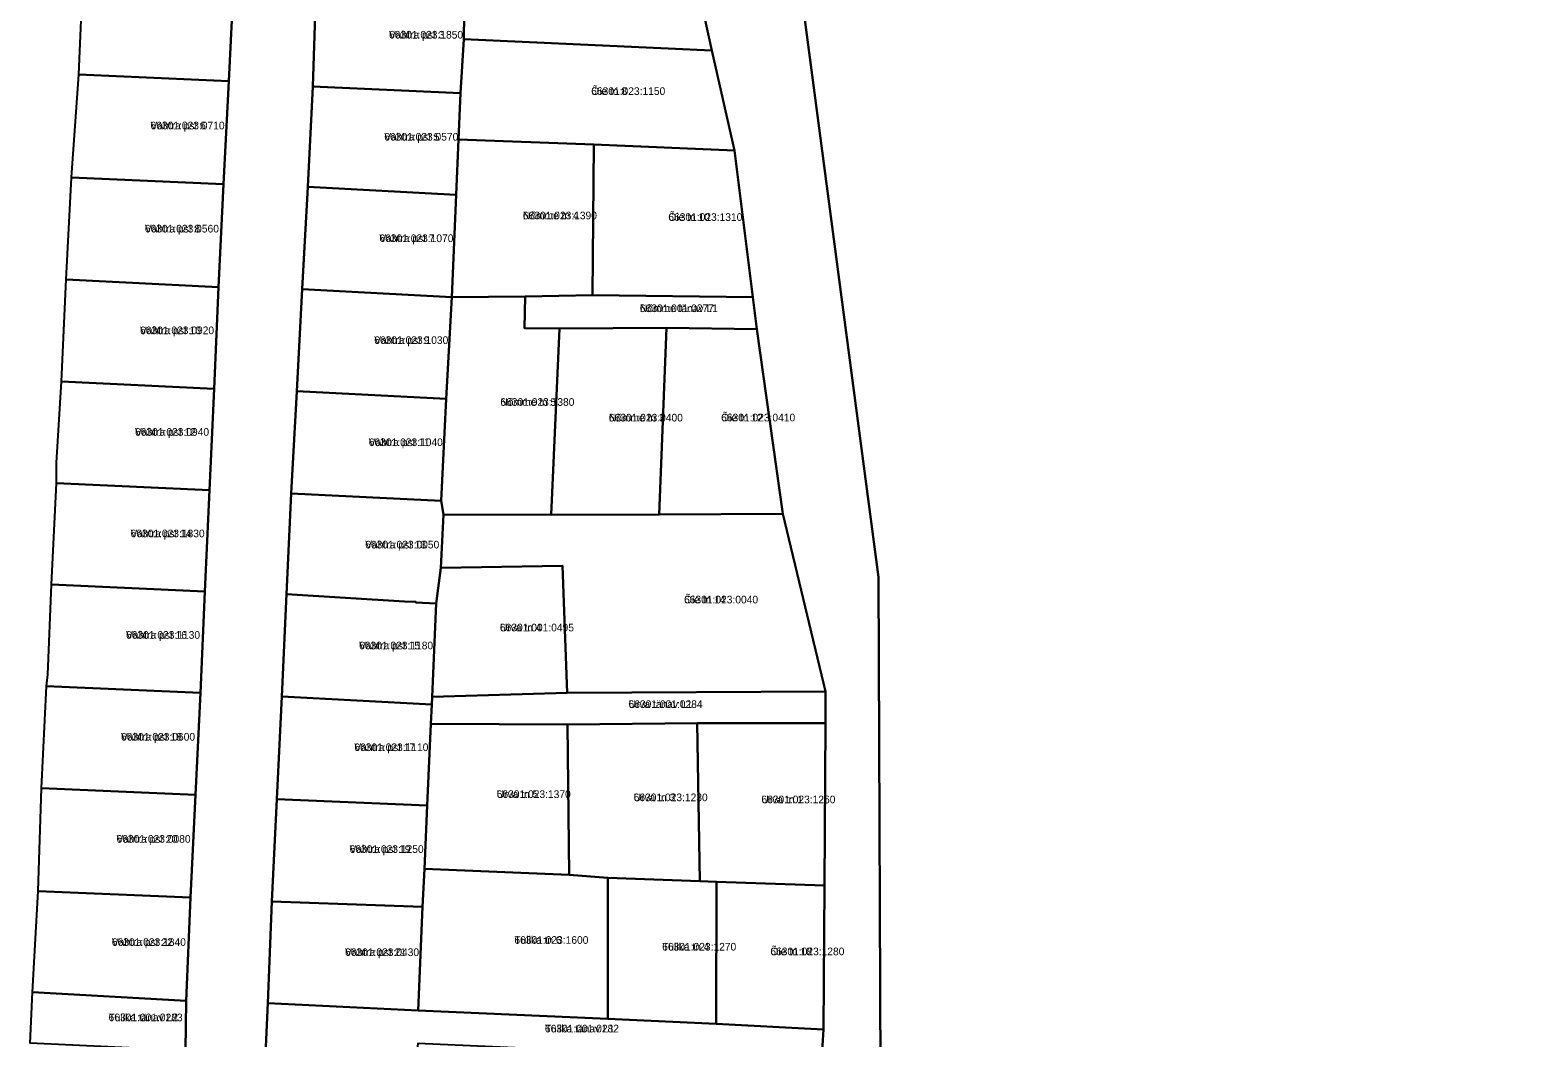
# Model space of a CAD drawing. Extents: x 632278 to 636344, y 6578401 to 6583362.
# Drawn here: x 633485.7 to 633781, y 6580259.1 to 6580456.5 of the extents above; entities that cross this region are included whole.
import ezdxf

# ---------------------------------------------------------------- set-up
doc = ezdxf.new("R2010")
doc.units = 0
for name, color, linetype in [('L_AADRESS', 7, 'Continuous'), ('PIIR', 7, 'Continuous'), ('TUNNUS', 7, 'Continuous')]:
    doc.layers.add(name, color=color, linetype=linetype)

msp = doc.modelspace()

# ---------------------------------------------------------------- linework, layer by layer
at = {"layer": 'PIIR'}
for points in [[(633605.51, 6579809.61), (633653.33, 6579978.24), (633651.84, 6580349.33), (633626.29, 6580542.71), (633673.01, 6580549.14), (633700.61, 6580504.19), (633703.74, 6580499.02), (633730.56, 6580496.56), (633754.85, 6580494.35), (633873.24, 6580487.78), (633957.63, 6580253.07), (633845.55, 6580021.57), (633842.59, 6580023.82), (633825.34, 6579983.05), (633800.65, 6579928), (633788.44, 6579901.57)], [(633626.29, 6580542.71), (633651.84, 6580349.33), (633653.33, 6579978.24), (633605.51, 6579809.61)], [(633640.7, 6580254.39), (633641.05, 6580260.68), (633641.28, 6580288.9), (633641.48, 6580320.75), (633641.44, 6580326.91), (633633.12, 6580361.74), (633628.04, 6580397.95), (633627.26, 6580404.2), (633623.67, 6580432.92), (633619.23, 6580452.53), (633613.69, 6580477.6)], [(633516.13, 6580256.6), (633516.28, 6580266.34), (633517.1, 6580286.58), (633518.11, 6580306.65), (633519.04, 6580326.64), (633519.93, 6580346.51), (633520.82, 6580366.38), (633521.71, 6580386.25), (633522.61, 6580406.13), (633523.54, 6580426.35), (633524.58, 6580446.52), (633525.58, 6580466.52)], [(633541.72, 6580465.57), (633541.03, 6580445.51), (633540.05, 6580425.81), (633538.98, 6580405.78), (633537.9, 6580385.76), (633536.82, 6580365.73), (633535.93, 6580346), (633534.97, 6580325.92), (633534, 6580305.84), (633533.03, 6580285.76), (633532.26, 6580265.84), (633531.82, 6580255.85)]]:
    msp.add_lwpolyline(points, dxfattribs=at)
for points in [[(633613.69, 6580477.6), (633619.23, 6580452.53), (633570.63, 6580454.73), (633570.76, 6580464.3), (633571.3, 6580479)], [(633496.08, 6580467.6), (633525.58, 6580466.52), (633524.58, 6580446.52), (633495.21, 6580447.82)], [(633541.72, 6580465.57), (633570.76, 6580464.3), (633570.63, 6580454.73), (633569.98, 6580444.18), (633541.03, 6580445.51)], [(633569.98, 6580444.18), (633570.63, 6580454.73), (633619.23, 6580452.53), (633623.67, 6580432.92), (633596.1, 6580434.1), (633569.61, 6580435.07)], [(633495.21, 6580447.82), (633524.58, 6580446.52), (633523.54, 6580426.35), (633493.8, 6580427.64)], [(633540.05, 6580425.81), (633541.03, 6580445.51), (633569.98, 6580444.18), (633569.61, 6580435.07), (633569.1, 6580424.25)], [(633568.3, 6580404.19), (633569.1, 6580424.25), (633569.61, 6580435.07), (633596.1, 6580434.1), (633595.85, 6580404.6), (633582.63, 6580404.31)], [(633596.1, 6580434.1), (633623.67, 6580432.92), (633627.26, 6580404.2), (633595.85, 6580404.6)], [(633493.8, 6580427.64), (633523.54, 6580426.35), (633522.61, 6580406.13), (633492.76, 6580407.65)], [(633540.05, 6580425.81), (633569.1, 6580424.25), (633568.3, 6580404.19), (633538.98, 6580405.78)], [(633492.76, 6580407.65), (633522.61, 6580406.13), (633521.71, 6580386.25), (633491.81, 6580387.69)], [(633538.98, 6580405.78), (633568.3, 6580404.19), (633567.17, 6580384.27), (633537.9, 6580385.76)], [(633566.19, 6580364.28), (633567.17, 6580384.27), (633568.3, 6580404.19), (633582.63, 6580404.31), (633582.54, 6580398.12), (633589.38, 6580398.05), (633587.71, 6580361.52), (633566.65, 6580361.6)], [(633582.63, 6580404.31), (633595.85, 6580404.6), (633627.26, 6580404.2), (633628.04, 6580397.95), (633610.34, 6580398.17), (633589.38, 6580398.05), (633582.54, 6580398.12)], [(633589.38, 6580398.05), (633610.34, 6580398.17), (633608.92, 6580361.64), (633587.71, 6580361.52)], [(633610.34, 6580398.17), (633628.04, 6580397.95), (633633.13, 6580361.74), (633608.92, 6580361.64)], [(633491.81, 6580387.69), (633521.71, 6580386.25), (633520.82, 6580366.38), (633490.85, 6580367.78), (633490.88, 6580371.76)], [(633537.9, 6580385.76), (633567.17, 6580384.27), (633566.19, 6580364.28), (633536.82, 6580365.73)], [(633490.85, 6580367.78), (633520.82, 6580366.38), (633519.93, 6580346.51), (633489.89, 6580347.87)], [(633536.82, 6580365.73), (633566.19, 6580364.28), (633566.65, 6580361.6), (633566.11, 6580351.16), (633565.23, 6580344.19), (633561.26, 6580344.38), (633561.24, 6580344.52), (633558.99, 6580344.57), (633535.93, 6580346)], [(633641.44, 6580326.91), (633590.84, 6580326.64), (633589.94, 6580351.53), (633566.11, 6580351.16), (633566.65, 6580361.6), (633587.71, 6580361.52), (633608.92, 6580361.64), (633633.13, 6580361.74)], [(633566.11, 6580351.16), (633589.94, 6580351.53), (633590.84, 6580326.64), (633564.43, 6580325.88), (633565.23, 6580344.19)], [(633489.89, 6580347.87), (633519.93, 6580346.51), (633519.04, 6580326.64), (633488.93, 6580327.95), (633489.15, 6580330.29)], [(633535.93, 6580346), (633558.99, 6580344.57), (633561.24, 6580344.52), (633561.26, 6580344.38), (633565.23, 6580344.19), (633564.43, 6580325.88), (633564.35, 6580324.38), (633534.97, 6580325.92)], [(633488.93, 6580327.95), (633519.04, 6580326.64), (633518.11, 6580306.65), (633487.92, 6580308)], [(633534.97, 6580325.92), (633564.35, 6580324.38), (633564.17, 6580320.56), (633563.45, 6580304.57), (633534, 6580305.84)], [(633564.43, 6580325.88), (633590.84, 6580326.64), (633641.44, 6580326.91), (633641.48, 6580320.75), (633616.34, 6580320.73), (633590.93, 6580320.48), (633564.17, 6580320.56), (633564.35, 6580324.38)], [(633563.45, 6580304.57), (633564.17, 6580320.56), (633590.93, 6580320.48), (633591.24, 6580290.99), (633562.9, 6580292.19)], [(633616.34, 6580320.73), (633616.85, 6580289.76), (633598.84, 6580290.44), (633591.24, 6580290.99), (633590.93, 6580320.48)], [(633616.85, 6580289.76), (633616.34, 6580320.73), (633641.48, 6580320.75), (633641.28, 6580288.9), (633620.13, 6580289.6)], [(633518.11, 6580306.65), (633517.1, 6580286.58), (633487.3, 6580287.81), (633487.92, 6580308)], [(633534, 6580305.84), (633563.45, 6580304.57), (633562.9, 6580292.19), (633562.56, 6580284.76), (633533.03, 6580285.76)], [(633562.56, 6580284.76), (633562.9, 6580292.19), (633591.24, 6580290.99), (633598.84, 6580290.44), (633598.82, 6580262.77), (633561.66, 6580264.42)], [(633598.84, 6580290.44), (633616.85, 6580289.76), (633620.13, 6580289.6), (633620.05, 6580261.78), (633598.82, 6580262.77)], [(633487.3, 6580287.81), (633517.1, 6580286.58), (633516.28, 6580266.34), (633486.15, 6580268.01)], [(633620.13, 6580289.6), (633641.28, 6580288.9), (633641.05, 6580260.68), (633620.05, 6580261.78)], [(633561.66, 6580264.42), (633532.26, 6580265.84), (633533.03, 6580285.76), (633562.56, 6580284.76)], [(633486.15, 6580268.01), (633516.28, 6580266.34), (633516.13, 6580256.6), (633485.7, 6580258.01)], [(633532.26, 6580265.84), (633561.66, 6580264.42), (633598.82, 6580262.77), (633620.05, 6580261.78), (633641.05, 6580260.68), (633640.7, 6580254.39), (633561.62, 6580257.97), (633561.25, 6580254.46), (633531.82, 6580255.85)]]:
    msp.add_lwpolyline(points, close=True, dxfattribs=at)

# ---------------------------------------------------------------- texts
at = {"layer": 'L_AADRESS'}
for s, p in [('Vahtra pst 3', (633555.99, 6580454.88)), ('Õie tn 8', (633595.58, 6580443.83)), ('Vahtra pst 6', (633509.28, 6580437.09)), ('Vahtra pst 5', (633555.05, 6580434.88)), ('Nõmme tn 4', (633582.2, 6580419.46)), ('Õie tn 10', (633610.68, 6580419.15)), ('Vahtra pst 8', (633508.17, 6580416.88)), ('Vahtra pst 7', (633554.1, 6580415)), ('Nõmme tänav L1', (633605.11, 6580401.28)), ('Vahtra pst 10', (633507.22, 6580396.95)), ('Vahtra pst 9', (633553.09, 6580395.03)), ('Nõmme tn 5', (633577.79, 6580382.91)), ('Õie tn 12', (633621.03, 6580379.86)), ('Vahtra pst 12', (633506.24, 6580377.04)), ('Nõmme tn 3', (633599.03, 6580379.84)), ('Vahtra pst 11', (633552.02, 6580375.02)), ('Vahtra pst 14', (633505.37, 6580357.15)), ('Vahtra pst 13', (633551.32, 6580354.96)), ('Õie tn 14', (633613.76, 6580344.19)), ('Urva tn 4', (633577.7, 6580338.71)), ('Vahtra pst 16', (633504.48, 6580337.26)), ('Vahtra pst 15', (633550.12, 6580335.19)), ('Urva tänav L1', (633602.89, 6580323.7)), ('Vahtra pst 18', (633503.5, 6580317.3)), ('Vahtra pst 17', (633549.19, 6580315.25)), ('Urva tn 5', (633577.07, 6580306.06)), ('Urva tn 3', (633603.89, 6580305.43)), ('Urva tn 1', (633628.91, 6580305.02)), ('Vahtra pst 20', (633502.62, 6580297.29)), ('Vahtra pst 19', (633548.26, 6580295.3)), ('Vahtra pst 22', (633501.7, 6580277.07)), ('Tulika tn 6', (633580.53, 6580277.48)), ('Vahtra pst 21', (633547.37, 6580275.09)), ('Tulika tn 4', (633609.48, 6580276.16)), ('Õie tn 18', (633630.66, 6580275.24)), ('Tulika tänav L2', (633501.06, 6580262.31)), ('Tulika tänav L1', (633586.51, 6580260.12))]:
    msp.add_text(s, height=1.5, dxfattribs=at).set_placement(p)
at = {"layer": 'TUNNUS'}
for s, p in [('66301:023:1850', (633555.99, 6580454.88)), ('66301:023:1150', (633595.58, 6580443.83)), ('66301:023:0710', (633509.28, 6580437.09)), ('66301:023:0570', (633555.05, 6580434.88)), ('66301:023:1390', (633582.2, 6580419.46)), ('66301:023:1310', (633610.68, 6580419.15)), ('66301:023:0560', (633508.17, 6580416.88)), ('66301:023:1070', (633554.1, 6580415)), ('66301:001:0277', (633605.11, 6580401.28)), ('66301:023:0920', (633507.22, 6580396.95)), ('66301:023:1030', (633553.09, 6580395.03)), ('66301:023:1380', (633577.79, 6580382.91)), ('66301:023:0400', (633599.03, 6580379.84)), ('66301:023:0410', (633621.03, 6580379.86)), ('66301:023:0940', (633506.24, 6580377.04)), ('66301:023:1040', (633552.02, 6580375.02)), ('66301:023:1830', (633505.37, 6580357.15)), ('66301:023:0050', (633551.32, 6580354.96)), ('66301:023:0040', (633613.76, 6580344.19)), ('66301:001:0495', (633577.7, 6580338.71)), ('66301:023:1130', (633504.48, 6580337.26)), ('66301:023:1180', (633550.12, 6580335.19)), ('66301:001:0284', (633602.89, 6580323.7)), ('66301:023:0600', (633503.5, 6580317.3)), ('66301:023:1110', (633549.19, 6580315.25)), ('66301:023:1370', (633577.07, 6580306.06)), ('66301:023:1230', (633603.89, 6580305.43)), ('66301:023:1260', (633628.91, 6580305.02)), ('66301:023:0080', (633502.62, 6580297.29)), ('66301:023:1250', (633548.26, 6580295.3)), ('66301:023:1840', (633501.7, 6580277.07)), ('66301:023:1600', (633580.53, 6580277.48)), ('66301:023:0430', (633547.37, 6580275.09)), ('66301:023:1270', (633609.48, 6580276.16)), ('66301:023:1280', (633630.66, 6580275.24)), ('66301:001:0283', (633501.06, 6580262.31)), ('66301:001:0282', (633586.51, 6580260.12))]:
    msp.add_text(s, height=1.5, dxfattribs=at).set_placement(p)

doc.saveas('drawing.dxf')
